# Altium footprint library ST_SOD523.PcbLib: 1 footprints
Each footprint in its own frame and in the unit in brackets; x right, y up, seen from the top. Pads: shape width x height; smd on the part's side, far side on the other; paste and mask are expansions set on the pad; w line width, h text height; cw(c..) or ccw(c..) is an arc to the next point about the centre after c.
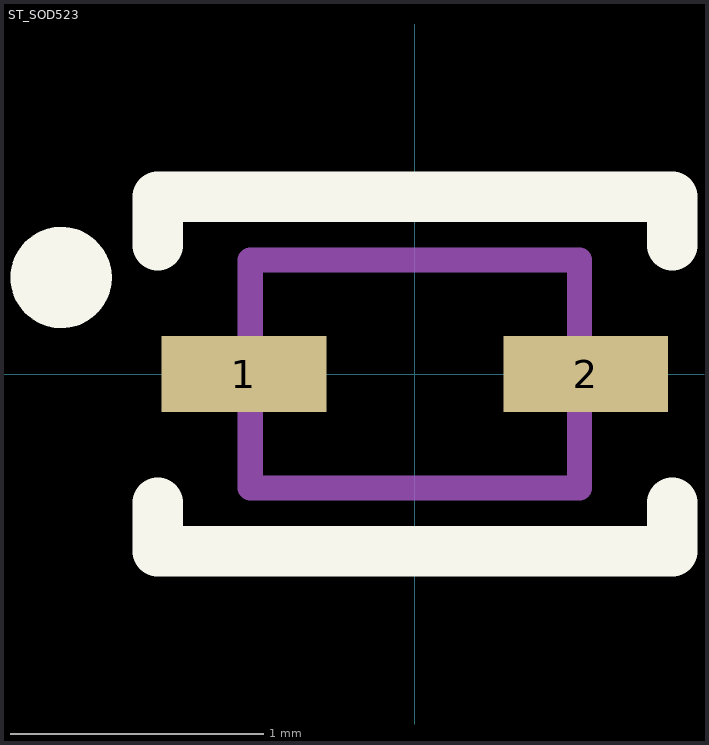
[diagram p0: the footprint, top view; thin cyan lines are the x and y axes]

## ST_SOD523 [mm] "ST_SOD523"
height 0.7
pads (2):
  rect 0.65x0.3 smd: 1(-0.675,0) 2(0.675,0)
Top Overlay:
  circle w0.2: c-1.397,0.381 r0.1
  lines w0.2: -1.016,-0.508 -1.016,-0.7 1.016,-0.7 1.016,-0.508 ; -1.016,0.508 -1.016,0.7 1.016,0.7 1.016,0.508
Mechanical 13:
  lines w0.1: -0.65,-0.45 0.65,-0.45 0.65,0.45 -0.65,0.45 -0.65,-0.45
3D body "ST_SOD523.step": height 0.7, standoff 0, extent -0.8,-0.45 0.8,0.45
